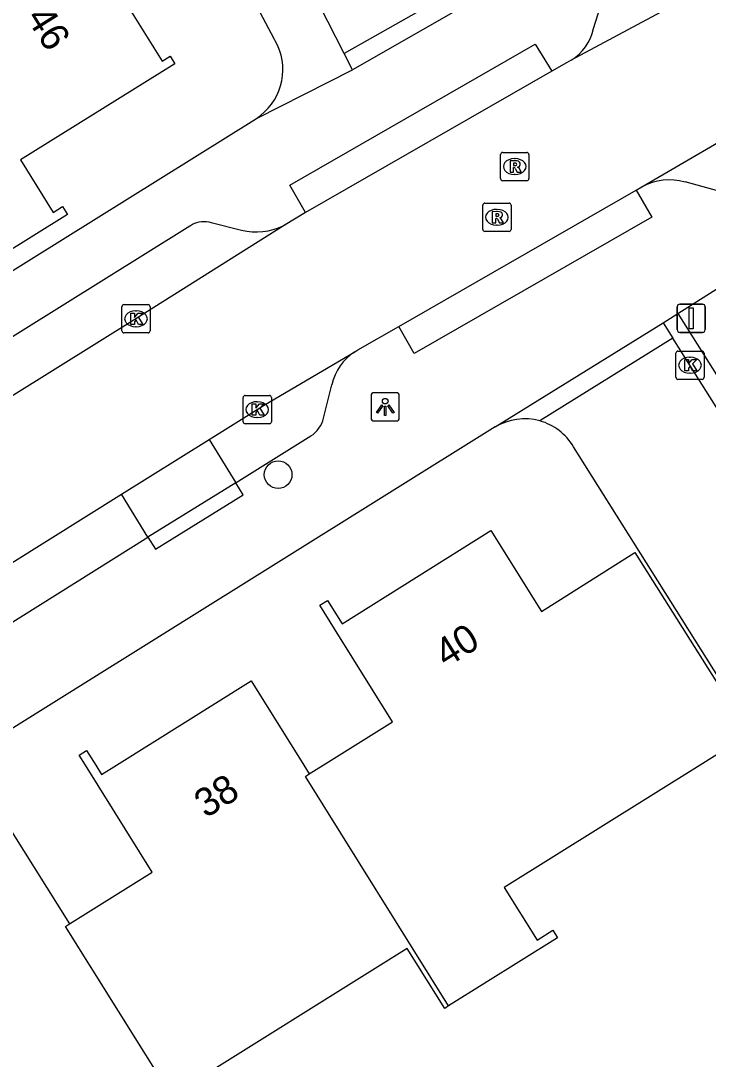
# Model space of a CAD drawing. Extents: x 158838 to 160074, y 386376 to 387776.
# Drawn here: x 159252.22 to 159276.51, y 386989.61 to 387026.31 of the extents above; entities that cross this region are included whole.
import ezdxf

# ---------------------------------------------------------------- set-up
doc = ezdxf.new("R2010")
doc.units = 0
for name, color, linetype in [('IMGEO_Boom', 7, 'Continuous'), ('IMGEO_Fietspad_open', 7, 'Continuous'), ('IMGEO_Kolk', 7, 'Continuous'), ('IMGEO_Lichtpunt', 7, 'Continuous'), ('IMGEO_Pand', 7, 'Continuous'), ('IMGEO_Pand_nummerreeks', 7, 'Continuous'), ('IMGEO_Parkeervlak_open', 7, 'Continuous'), ('IMGEO_Rijbaan_lokaal_open', 7, 'Continuous'), ('IMGEO_Rioolput', 7, 'Continuous'), ('IMGEO_Verkeersbordpaal', 7, 'Continuous'), ('IMGEO_Verkeerseiland_open', 7, 'Continuous'), ('IMGEO_Voetpad_open', 7, 'Continuous')]:
    doc.layers.add(name, color=color, linetype=linetype)

msp = doc.modelspace()

# ---------------------------------------------------------------- linework, layer by layer
at = {"layer": 'IMGEO_Boom'}
msp.add_circle((159261.312, 387010.265), 0.489, dxfattribs=at)
at = {"layer": 'IMGEO_Fietspad_open'}
for points in [[(159272.455, 387026.033), (159274.924, 387033.811)], [(159285.09, 387018.012), (159275.697, 387020.61)]]:
    msp.add_lwpolyline(points, dxfattribs=at)
for centre, radius, start, end in [((159270.76, 387026.386), 1.732, 301.5969, 348.241), ((159275.148, 387018.54), 2.141, 75.1502, 117.2422)]:
    msp.add_arc(centre, radius, start, end, dxfattribs=at)
at = {"layer": 'IMGEO_Kolk'}
for p, q in [((159255.787, 387015.35), (159255.787, 387016.202)), ((159255.862, 387016.276), (159256.714, 387016.276)), ((159256.275, 387016.056), (159256.3, 387016.056)), ((159256.788, 387016.202), (159256.788, 387015.35)), ((159256.298, 387015.496), (159256.273, 387015.496)), ((159256.714, 387015.276), (159255.862, 387015.276)), ((159275.443, 387014.635), (159276.295, 387014.635)), ((159275.368, 387013.709), (159275.368, 387014.561)), ((159275.856, 387014.415), (159275.881, 387014.415)), ((159276.369, 387014.561), (159276.369, 387013.709)), ((159275.879, 387013.855), (159275.854, 387013.855)), ((159276.295, 387013.635), (159275.443, 387013.635)), ((159260.074, 387012.139), (159260.074, 387012.991)), ((159260.149, 387013.065), (159261.001, 387013.065)), ((159260.562, 387012.845), (159260.587, 387012.845)), ((159261.075, 387012.991), (159261.075, 387012.139)), ((159261.001, 387012.065), (159260.149, 387012.065)), ((159260.585, 387012.285), (159260.56, 387012.285))]:
    msp.add_line(p, q, dxfattribs=at)
for points in [[(159255.787, 387015.35), (159255.787, 387016.202)], [(159255.862, 387016.276), (159256.714, 387016.276)], [(159256.788, 387016.202), (159256.788, 387015.35)], [(159256.108, 387015.976), (159256.231, 387015.976), (159256.231, 387015.825), (159256.361, 387015.976), (159256.525, 387015.976), (159256.379, 387015.825), (159256.532, 387015.576), (159256.38, 387015.576), (159256.295, 387015.74), (159256.231, 387015.673), (159256.231, 387015.576), (159256.108, 387015.576), (159256.108, 387015.976)], [(159256.714, 387015.276), (159255.862, 387015.276)], [(159275.443, 387014.635), (159276.295, 387014.635)], [(159275.368, 387013.709), (159275.368, 387014.561)], [(159275.689, 387014.335), (159275.812, 387014.335), (159275.812, 387014.184), (159275.942, 387014.335), (159276.106, 387014.335), (159275.96, 387014.184), (159276.113, 387013.935), (159275.961, 387013.935), (159275.876, 387014.099), (159275.812, 387014.032), (159275.812, 387013.935), (159275.689, 387013.935), (159275.689, 387014.335)], [(159276.369, 387014.561), (159276.369, 387013.709)], [(159276.295, 387013.635), (159275.443, 387013.635)], [(159260.074, 387012.139), (159260.074, 387012.991)], [(159260.149, 387013.065), (159261.001, 387013.065)], [(159260.395, 387012.765), (159260.518, 387012.765), (159260.518, 387012.614), (159260.648, 387012.765), (159260.812, 387012.765), (159260.666, 387012.614), (159260.819, 387012.365), (159260.667, 387012.365), (159260.582, 387012.529), (159260.518, 387012.462), (159260.518, 387012.365), (159260.395, 387012.365), (159260.395, 387012.765)], [(159261.075, 387012.991), (159261.075, 387012.139)], [(159261.001, 387012.065), (159260.149, 387012.065)]]:
    msp.add_lwpolyline(points, dxfattribs=at)
for centre, start, end in [((159255.864, 387016.2), 91.552, 178.448), ((159255.864, 387016.2), 91.552, 178.448), ((159256.712, 387016.2), 1.552, 88.448), ((159256.712, 387016.2), 1.552, 88.448), ((159255.864, 387015.352), 181.552, 268.448), ((159255.864, 387015.352), 181.552, 268.448), ((159256.712, 387015.352), 271.552, 358.448), ((159256.712, 387015.352), 271.552, 358.448), ((159275.445, 387014.559), 91.552, 178.448), ((159275.445, 387014.559), 91.552, 178.448), ((159276.293, 387014.559), 1.552, 88.448), ((159276.293, 387014.559), 1.552, 88.448), ((159275.445, 387013.711), 181.552, 268.448), ((159275.445, 387013.711), 181.552, 268.448), ((159276.293, 387013.711), 271.552, 358.448), ((159276.293, 387013.711), 271.552, 358.448), ((159260.151, 387012.989), 91.552, 178.448), ((159260.151, 387012.989), 91.552, 178.448), ((159260.999, 387012.989), 1.552, 88.448), ((159260.999, 387012.989), 1.552, 88.448), ((159260.151, 387012.141), 181.552, 268.448), ((159260.151, 387012.141), 181.552, 268.448), ((159260.999, 387012.141), 271.552, 358.448), ((159260.999, 387012.141), 271.552, 358.448)]:
    msp.add_arc(centre, 0.0765, start, end, dxfattribs=at)
for centre, major_axis, ratio, start_param, end_param in [((159256.274, 387015.776), (-0.387, 0.002), 0.722429, 4.712389, 7.853982), ((159256.299, 387015.776), (-0.39, 0.002), 0.717154, 1.570796, 4.712389), ((159275.855, 387014.135), (-0.387, 0.002), 0.722429, 4.712389, 7.853982), ((159275.88, 387014.135), (-0.39, 0.002), 0.717154, 1.570796, 4.712389), ((159260.561, 387012.565), (-0.387, 0.002), 0.722429, 4.712389, 7.853982), ((159260.586, 387012.565), (-0.39, 0.002), 0.717154, 1.570796, 4.712389)]:
    msp.add_ellipse(centre, major_axis=major_axis, ratio=ratio, start_param=start_param, end_param=end_param, dxfattribs=at)
at = {"layer": 'IMGEO_Lichtpunt'}
for p, q in [((159265.5, 387013.161), (159264.692, 387013.161)), ((159265.5, 387013.161), (159264.692, 387013.161)), ((159264.598, 387013.066), (159264.598, 387012.259)), ((159264.598, 387013.066), (159264.598, 387012.259)), ((159265.594, 387012.259), (159265.594, 387013.066)), ((159265.594, 387012.259), (159265.594, 387013.066)), ((159264.692, 387012.165), (159265.5, 387012.165)), ((159264.692, 387012.165), (159265.5, 387012.165))]:
    msp.add_line(p, q, dxfattribs=at)
for points in [[(159264.972, 387012.73), (159265.011, 387012.702), (159264.823, 387012.44), (159264.785, 387012.467), (159264.972, 387012.73)], [(159265.074, 387012.682), (159265.121, 387012.682), (159265.121, 387012.36), (159265.074, 387012.36), (159265.074, 387012.682)], [(159265.184, 387012.702), (159265.222, 387012.729), (159265.409, 387012.467), (159265.37, 387012.439), (159265.184, 387012.702)]]:
    msp.add_lwpolyline(points, dxfattribs=at)
msp.add_circle((159265.097, 387012.864), 0.0994, dxfattribs=at)
for centre, start, end in [((159264.692, 387013.066), 90, 180), ((159264.692, 387013.066), 90, 180), ((159265.5, 387013.066), 0, 90), ((159265.5, 387013.066), 0, 90), ((159264.692, 387012.259), 180, 270), ((159264.692, 387012.259), 180, 270), ((159265.5, 387012.259), 270, 0), ((159265.5, 387012.259), 270, 360)]:
    msp.add_arc(centre, 0.0946, start, end, dxfattribs=at)
at = {"layer": 'IMGEO_Pand'}
for points in [[(159253.357, 387032.896), (159253.442, 387032.76), (159251.286, 387031.433), (159252.65, 387029.217), (159254.063, 387026.986), (159255.383, 387027.811), (159257.214, 387024.885), (159257.494, 387025.06), (159257.664, 387024.789), (159252.205, 387021.394), (159253.363, 387019.532), (159253.695, 387019.738), (159253.864, 387019.466), (159249.1, 387016.492), (159247.571, 387018.938), (159244.789, 387017.2), (159240.22, 387024.511), (159243.003, 387026.25), (159242.922, 387026.379)], [(159262.41, 386999.69), (159262.905, 387000), (159265.356, 387001.534), (159263.301, 387004.819), (159262.789, 387005.654), (159263.052, 387005.822), (159263.574, 387004.99), (159268.834, 387008.291), (159270.618, 387005.436), (159273.925, 387007.511), (159277.969, 387001.09), (159276.224, 387000), (159269.305, 386995.677), (159270.465, 386993.821), (159271.015, 386994.165), (159271.185, 386993.894), (159267.338, 386991.491)], [(159253.934, 386994.388), (159256.864, 386996.221), (159254.5, 387000), (159254.279, 387000.354), (159254.542, 387000.518), (159254.866, 387000), (159255.072, 386999.67), (159255.599, 387000), (159260.355, 387002.976), (159262.216, 387000), (159262.41, 386999.69)], [(159267.338, 386991.491), (159262.274, 386999.605), (159262.41, 386999.69)], [(159245.45, 386989.081), (159248.388, 386990.919), (159245.803, 386995.052), (159246.066, 386995.216), (159246.596, 386994.369), (159251.879, 386997.674), (159253.934, 386994.388)], [(159257.54, 386988.314), (159253.798, 386994.303), (159253.934, 386994.388)], [(159267.338, 386991.491), (159267.202, 386991.406), (159265.878, 386993.524), (159257.54, 386988.314)]]:
    msp.add_lwpolyline(points, dxfattribs=at)
at = {"layer": 'IMGEO_Parkeervlak_open'}
for points in [[(159258.872, 387011.507), (159259.816, 387009.98)], [(159256.712, 387008.062), (159255.77, 387009.572)]]:
    msp.add_lwpolyline(points, dxfattribs=at)
at = {"layer": 'IMGEO_Rijbaan_lokaal_open'}
for points in [[(159263.643, 387025.149), (159262.771, 387026.855), (159259.501, 387033.04)], [(159268.082, 387027.672), (159263.643, 387025.149)], [(159268.337, 387027.091), (159263.939, 387024.57)], [(159276.002, 387027.248), (159271.667, 387024.911)], [(159263.939, 387024.57), (159263.643, 387025.149)], [(159271.667, 387024.911), (159271.499, 387024.821), (159270.99, 387024.527)], [(159270.99, 387024.527), (159262.282, 387019.531)], [(159274.168, 387020.444), (159278.376, 387022.888)], [(159273.969, 387020.317), (159274.168, 387020.444)], [(159265.576, 387015.505), (159273.969, 387020.317)], [(159262.282, 387019.531), (159261.556, 387019.098)], [(159261.556, 387019.098), (159256.284, 387015.775), (159243.206, 387007.623), (159231.021, 387000), (159228.706, 386998.552)], [(159264.021, 387014.611), (159264.131, 387014.676), (159265.576, 387015.505)], [(159268.983, 387011.952), (159274.92, 387015.636)], [(159274.92, 387015.636), (159275.266, 387015.086)], [(159275.266, 387015.086), (159270.561, 387012.166)], [(159322.715, 386930.535), (159321.43, 386932.941), (159304.466, 386964.768), (159295.073, 386982.492), (159291.692, 386988.882), (159291.192, 386989.757), (159290.67, 386990.608), (159286.562, 386997.204), (159284.795, 387000), (159275.864, 387014.134), (159275.266, 387015.086)], [(159258.872, 387011.507), (159260.57, 387012.566), (159260.791, 387012.712), (159264.021, 387014.611)], [(159255.77, 387009.572), (159258.872, 387011.507)], [(159317.722, 386929.245), (159312.67, 386938.746), (159307.356, 386948.741), (159287.3, 386986.46), (159286.81, 386987.307), (159278.827, 387000), (159271.75, 387011.252)], [(159250.622, 387006.361), (159255.77, 387009.572)]]:
    msp.add_lwpolyline(points, dxfattribs=at)
for centre, radius, start, end in [((159270.02, 387010.231), 2.009, 74.3799, 121.0662), ((159270.019, 387010.231), 2.01, 30.5451, 74.355)]:
    msp.add_arc(centre, radius, start, end, dxfattribs=at)
at = {"layer": 'IMGEO_Rioolput'}
for p, q in [((159269.174, 387020.729), (159269.174, 387021.581)), ((159269.249, 387021.655), (159270.101, 387021.655)), ((159270.175, 387021.581), (159270.175, 387020.729)), ((159269.662, 387021.435), (159269.687, 387021.435)), ((159269.685, 387020.875), (159269.66, 387020.875)), ((159270.101, 387020.655), (159269.249, 387020.655)), ((159268.545, 387018.936), (159268.545, 387019.788)), ((159268.62, 387019.862), (159269.472, 387019.862)), ((159269.546, 387019.788), (159269.546, 387018.936)), ((159269.033, 387019.642), (159269.058, 387019.642)), ((159269.056, 387019.082), (159269.031, 387019.082)), ((159269.472, 387018.862), (159268.62, 387018.862))]:
    msp.add_line(p, q, dxfattribs=at)
for points in [[(159269.174, 387020.729), (159269.174, 387021.581)], [(159269.249, 387021.655), (159270.101, 387021.655)], [(159270.175, 387021.581), (159270.175, 387020.729)], [(159269.763, 387021.353), (159269.511, 387021.355), (159269.511, 387020.955)], [(159269.689, 387021.274), (159269.635, 387021.274), (159269.635, 387021.193)], [(159269.635, 387021.193), (159269.687, 387021.193)], [(159269.511, 387020.955), (159269.635, 387020.955), (159269.635, 387021.117), (159269.646, 387021.117)], [(159269.693, 387021.088), (159269.764, 387020.955), (159269.904, 387020.955), (159269.839, 387021.081)], [(159270.101, 387020.655), (159269.249, 387020.655)], [(159268.545, 387018.936), (159268.545, 387019.788)], [(159268.62, 387019.862), (159269.472, 387019.862)], [(159269.546, 387019.788), (159269.546, 387018.936)], [(159269.134, 387019.56), (159268.882, 387019.562), (159268.882, 387019.162)], [(159269.06, 387019.481), (159269.006, 387019.481), (159269.006, 387019.4)], [(159269.006, 387019.4), (159269.058, 387019.4)], [(159268.882, 387019.162), (159269.006, 387019.162), (159269.006, 387019.324), (159269.017, 387019.324)], [(159269.064, 387019.295), (159269.135, 387019.162), (159269.275, 387019.162), (159269.21, 387019.288)], [(159269.472, 387018.862), (159268.62, 387018.862)]]:
    msp.add_lwpolyline(points, dxfattribs=at)
for centre, radius, start, end in [((159269.251, 387021.579), 0.0765, 91.552, 178.448), ((159269.251, 387021.579), 0.0765, 91.552, 178.448), ((159270.099, 387021.579), 0.0765, 1.552, 88.448), ((159270.099, 387021.579), 0.0765, 1.552, 88.448), ((159269.671, 387021.382), 0.19, 274.7715, 282.9687), ((159269.695, 387021.178), 0.0964, 77.0061, 93.1865), ((159269.709, 387021.235), 0.0378, 276.6634, 79.6772), ((159269.762, 387021.243), 0.109, 350.3612, 89.416), ((159269.76, 387021.243), 0.112, 277.5842, 350.9817), ((159269.645, 387021.064), 0.0533, 26.0293, 88.6989), ((159269.744, 387021.028), 0.108, 29.5134, 73.7905), ((159269.251, 387020.731), 0.0765, 181.552, 268.448), ((159269.251, 387020.731), 0.0765, 181.552, 268.448), ((159270.099, 387020.731), 0.0765, 271.552, 358.448), ((159270.099, 387020.731), 0.0765, 271.552, 358.448), ((159268.622, 387019.786), 0.0765, 91.552, 178.448), ((159268.622, 387019.786), 0.0765, 91.552, 178.448), ((159269.47, 387019.786), 0.0765, 1.552, 88.448), ((159269.47, 387019.786), 0.0765, 1.552, 88.448), ((159269.042, 387019.589), 0.19, 274.7715, 282.9687), ((159269.066, 387019.385), 0.0964, 77.0061, 93.1865), ((159269.08, 387019.442), 0.0378, 276.6634, 79.6772), ((159269.133, 387019.45), 0.109, 350.3612, 89.416), ((159269.131, 387019.45), 0.112, 277.5842, 350.9817), ((159269.016, 387019.271), 0.0533, 26.0293, 88.6989), ((159269.115, 387019.235), 0.108, 29.5134, 73.7905), ((159268.622, 387018.938), 0.0765, 181.552, 268.448), ((159268.622, 387018.938), 0.0765, 181.552, 268.448), ((159269.47, 387018.938), 0.0765, 271.552, 358.448), ((159269.47, 387018.938), 0.0765, 271.552, 358.448)]:
    msp.add_arc(centre, radius, start, end, dxfattribs=at)
for centre, major_axis, ratio, start_param, end_param in [((159269.661, 387021.155), (-0.387, 0.002), 0.722429, 4.712389, 7.853982), ((159269.686, 387021.155), (-0.39, 0.002), 0.717154, 1.570796, 4.712389), ((159269.032, 387019.362), (-0.387, 0.002), 0.722429, 4.712389, 7.853982), ((159269.057, 387019.362), (-0.39, 0.002), 0.717154, 1.570796, 4.712389)]:
    msp.add_ellipse(centre, major_axis=major_axis, ratio=ratio, start_param=start_param, end_param=end_param, dxfattribs=at)
at = {"layer": 'IMGEO_Verkeersbordpaal'}
for p, q in [((159275.415, 387015.392), (159275.415, 387016.192)), ((159275.415, 387016.192), (159275.415, 387015.392)), ((159275.515, 387016.292), (159276.305, 387016.292)), ((159276.305, 387016.292), (159275.515, 387016.292)), ((159276.405, 387016.192), (159276.405, 387015.392)), ((159276.405, 387015.392), (159276.405, 387016.192)), ((159276.305, 387015.292), (159275.515, 387015.292)), ((159275.515, 387015.292), (159276.305, 387015.292))]:
    msp.add_line(p, q, dxfattribs=at)
msp.add_lwpolyline([(159275.835, 387016.167), (159275.985, 387016.167), (159275.985, 387015.417), (159275.835, 387015.417), (159275.835, 387016.167)], dxfattribs=at)
for centre, start, end in [((159275.515, 387016.192), 90, 180), ((159275.515, 387016.192), 90, 180), ((159276.305, 387016.192), 0, 90), ((159276.305, 387016.192), 360, 90), ((159275.515, 387015.392), 180, 270), ((159275.515, 387015.392), 180, 270), ((159276.305, 387015.392), 270, 0), ((159276.305, 387015.392), 270, 0)]:
    msp.add_arc(centre, 0.1, start, end, dxfattribs=at)
at = {"layer": 'IMGEO_Verkeerseiland_open'}
msp.add_lwpolyline([(159275.437, 387015.961), (159285.506, 387000), (159287.099, 386997.475), (159291.489, 386990.45), (159291.972, 386989.668), (159292.393, 386988.851), (159323.247, 386930.836), (159322.715, 386930.535)], dxfattribs=at)
at = {"layer": 'IMGEO_Voetpad_open'}
for points in [[(159260.545, 387022.859), (159260.694, 387022.965), (159260.833, 387023.084), (159260.961, 387023.215), (159261.077, 387023.357), (159261.18, 387023.509), (159261.268, 387023.669), (159261.342, 387023.836), (159261.401, 387024.01), (159261.444, 387024.188), (159261.471, 387024.369), (159261.482, 387024.552), (159261.476, 387024.735), (159261.454, 387024.916), (159261.416, 387025.096), (159261.362, 387025.271), (159261.292, 387025.44), (159261.208, 387025.602), (159261.184, 387025.643), (159192.812, 387154.528)], [(159262.282, 387019.531), (159261.725, 387020.502), (159270.396, 387025.477), (159270.99, 387024.527)], [(159260.545, 387022.859), (159263.939, 387024.57)], [(159224.402, 387000.372), (159224.563, 387000.43), (159224.717, 387000.503), (159224.864, 387000.59), (159224.937, 387000.639), (159235.813, 387007.426), (159250.297, 387016.464), (159260.545, 387022.859)], [(159273.969, 387020.317), (159274.516, 387019.363), (159266.123, 387014.551), (159265.576, 387015.505)], [(159228.538, 387000.563), (159258.19, 387019.064), (159258.209, 387019.076), (159258.284, 387019.117), (159258.362, 387019.15), (159258.442, 387019.177), (159258.525, 387019.197), (159258.609, 387019.209), (159258.694, 387019.213), (159258.779, 387019.21), (159258.863, 387019.199), (159258.946, 387019.181), (159260.021, 387018.911), (159260.206, 387018.872), (159260.393, 387018.849), (159260.582, 387018.844), (159260.771, 387018.855), (159260.958, 387018.883), (159261.141, 387018.928), (159261.32, 387018.989), (159261.493, 387019.065), (159261.556, 387019.098)], [(159275.437, 387015.961), (159278.388, 387017.823), (159283.6, 387016.408)], [(159274.92, 387015.636), (159275.437, 387015.961)], [(159262.915, 387012.266), (159263.214, 387013.446)], [(159268.983, 387011.952), (159249.829, 387000), (159232.183, 386988.989)], [(159259.816, 387009.98), (159259.923, 387010.046), (159262.467, 387011.634)], [(159259.816, 387009.98), (159256.712, 387008.062)], [(159256.712, 387008.062), (159256.974, 387007.637), (159260.079, 387009.555), (159259.816, 387009.98)], [(159251.574, 387004.839), (159251.619, 387004.867), (159256.712, 387008.062)]]:
    msp.add_lwpolyline(points, dxfattribs=at)
for centre, radius, start, end in [((159265.002, 387013.069), 1.827, 122.4711, 168.108), ((159261.932, 387012.488), 1.008, 302.0623, 347.275)]:
    msp.add_arc(centre, radius, start, end, dxfattribs=at)

# ---------------------------------------------------------------- texts
at = {"layer": 'IMGEO_Pand_nummerreeks'}
for s, rotation, p in [('46', 302.0339, (159252.383, 387026.424)), ('40', 32.111, (159267.251, 387003.424)), ('38', 32.0375, (159258.757, 386998.107))]:
    msp.add_text(s, height=1, rotation=rotation, dxfattribs=at).set_placement(p)

doc.saveas('drawing.dxf')
